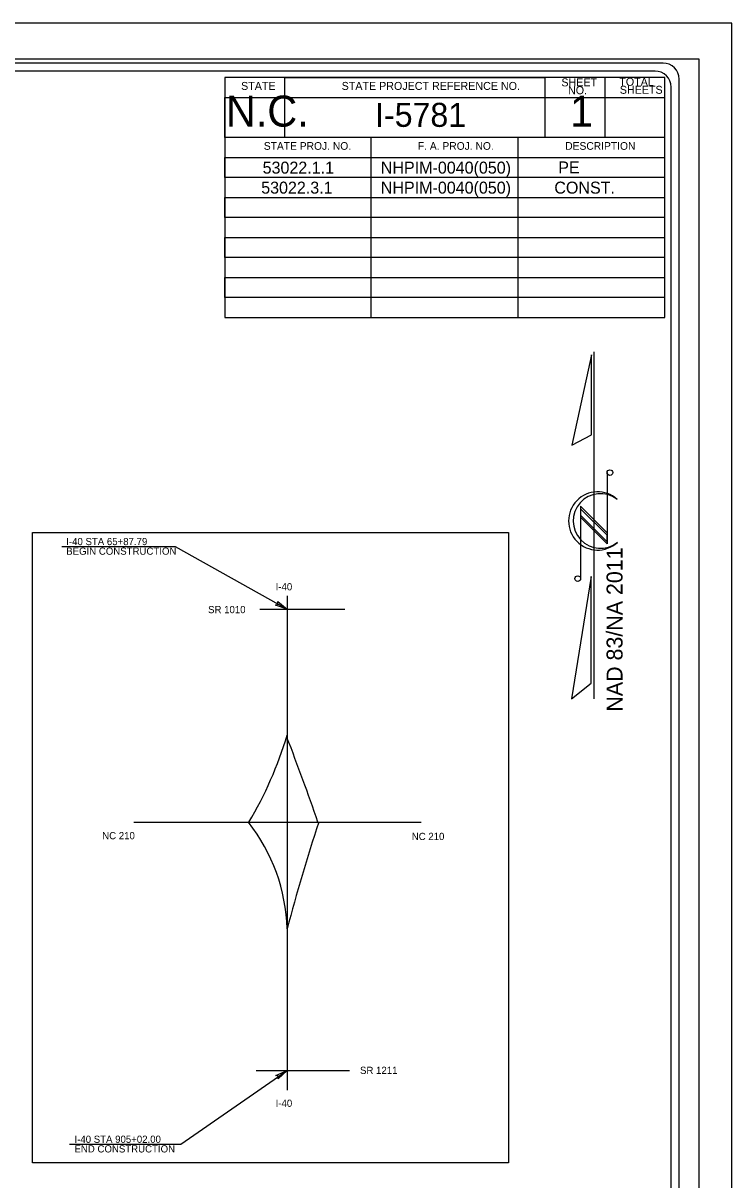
# Model space of a CAD drawing. Extents: x 2128934 to 2134034, y 641595 to 644895.
# Drawn here: x 2132705 to 2134034, y 642727 to 644895 of the extents above; entities that cross this region are included whole.
import ezdxf

# ---------------------------------------------------------------- set-up
doc = ezdxf.new("R2010")
doc.units = 0
for name, color, linetype in [('Prop Dimension Text', 7, 'Continuous'), ('Prop DSN Text', 7, 'Continuous'), ('Prop Horizontal Alignment', 7, 'Continuous'), ('Prop Terminator CELL', 7, 'Continuous'), ('Sheet Data Field CELL', 7, 'Continuous'), ('Sheet North Arrow CELL', 7, 'Continuous'), ('Sheet Plot Border Inside CELL', 7, 'Continuous'), ('Sheet Plot Border Outside CELL', 7, 'Continuous'), ('Sheet Title CELL', 7, 'Continuous')]:
    doc.layers.add(name, color=color, linetype=linetype)

msp = doc.modelspace()

# ---------------------------------------------------------------- linework, layer by layer
at = {"layer": 'Prop Dimension Text'}
for p, q in [((2132777.5, 643914.2), (2132989.6, 643914.2)), ((2132989.6, 643914.2), (2133199.9, 643796.5)), ((2133000.2, 642793.7), (2133199.9, 642931.7)), ((2132791.7, 642793.6), (2133000.2, 642793.7))]:
    msp.add_line(p, q, dxfattribs=at)
at = {"layer": 'Prop DSN Text'}
msp.add_lwpolyline([(2132722.5, 643940.6), (2133614.8, 643940.6), (2133614.8, 642758.6), (2132722.5, 642758.6)], close=True, dxfattribs=at)
at = {"layer": 'Prop Horizontal Alignment'}
for p, q in [((2133199.9, 643821.3), (2133199.9, 642894.9)), ((2133148.4, 643796.5), (2133308.2, 643796.5)), ((2132912.1, 643397.1), (2133451.2, 643397.1)), ((2133141.5, 642931.7), (2133316.5, 642931.7))]:
    msp.add_line(p, q, dxfattribs=at)
for centre, radius, start, end in [((2132503.8, 643770.2), 727.1, 329.1308, 343.2184), ((2128978.9, 641925.5), 4524.7, 18.9803, 21.1256), ((2132859.4, 643187.1), 340.6, 1.7123, 38.08), ((2136013.3, 642470.8), 2905.7, 161.4088, 165.5242)]:
    msp.add_arc(centre, radius, start, end, dxfattribs=at)
at = {"layer": 'Prop Terminator CELL'}
for points in [[(2133182.1, 643810.9), (2133199.9, 643796.5), (2133178.2, 643804.1), (2133182.6, 643806.1)], [(2133178.9, 642922.8), (2133199.9, 642931.7), (2133183, 642916.1), (2133183.3, 642921)]]:
    msp.add_lwpolyline(points, close=True, dxfattribs=at)
at = {"layer": 'Sheet North Arrow CELL'}
for p, q in [((2133775.3, 643628.8), (2133775.3, 644278.8)), ((2133799.8, 644052.6), (2133799.8, 643919.2)), ((2133818.2, 644002.9), (2133818.9, 644002.4)), ((2133799.8, 643940), (2133750.1, 643989.7)), ((2133750.1, 643989.7), (2133750.1, 643854.1)), ((2133799.8, 643935.1), (2133750.1, 643984.8)), ((2133750.1, 643984.8), (2133750.1, 643972.6)), ((2133799.8, 643922.9), (2133750.1, 643972.6)), ((2133750.1, 643972.6), (2133799.8, 643922.9)), ((2133799.8, 643919.2), (2133750.1, 643968.9)), ((2133799.8, 643922.9), (2133799.8, 643935.1))]:
    msp.add_line(p, q, dxfattribs=at)
for points in [[(2133770.8, 644273.1), (2133733.7, 644104.3), (2133770.8, 644123.1)], [(2133770, 643857.8), (2133733.2, 643628.8), (2133770, 643657.8)]]:
    msp.add_lwpolyline(points, close=True, dxfattribs=at)
for centre in [(2133805.1, 644052.5), (2133744.8, 643853.9)]:
    msp.add_circle(centre, 5.3, dxfattribs=at)
for centre, radius, start, end in [((2133782.2, 643962), 54.6, 47.84, 312.3941), ((2133787.5, 643962), 51.2, 53.095, 308.6287)]:
    msp.add_arc(centre, radius, start, end, dxfattribs=at)
at = {"layer": 'Sheet Plot Border Inside CELL'}
msp.add_lwpolyline([(2128972.8, 641662.5), (2133972.3, 641662.5), (2133972.3, 644827.8), (2128972.8, 644827.8)], close=True, dxfattribs=at)
at = {"layer": 'Sheet Plot Border Outside CELL'}
msp.add_lwpolyline([(2128933.8, 641595.1), (2134033.8, 641595.1), (2134033.8, 644895.1), (2128933.8, 644895.1)], close=True, dxfattribs=at)
at = {"layer": 'Sheet Title CELL'}
for points in [[(2133904.8, 644820.1), (2129464.7, 644820.2)], [(2133889.8, 644805.1), (2129629.8, 644805.1)], [(2133082.8, 644343.2), (2133907.8, 644343.2), (2133907.8, 644380.6), (2133082.8, 644380.7), (2133082.8, 644418.1), (2133907.8, 644418.1), (2133907.8, 644455.6), (2133082.8, 644455.6), (2133082.8, 644493.2), (2133907.8, 644493.2), (2133907.8, 644530.7), (2133082.8, 644530.7), (2133082.8, 644568.1), (2133907.8, 644568.2), (2133907.8, 644605.6), (2133082.8, 644605.6), (2133082.8, 644643.1), (2133907.8, 644643.1), (2133907.8, 644680.7), (2133082.8, 644680.7), (2133082.8, 644755.7), (2133907.8, 644755.7), (2133907.8, 644793.2), (2133082.8, 644793.1), (2133082.8, 644343.2), (2133357.7, 644343.1), (2133357.7, 644680.6), (2133195.3, 644680.6), (2133195.3, 644793.2), (2133682.8, 644793.1), (2133682.8, 644680.7), (2133632.7, 644680.7), (2133632.7, 644343.2), (2133907.8, 644343.2), (2133907.8, 644793.2), (2133795.3, 644793.2), (2133795.3, 644680.7)], [(2133919.8, 642270.1), (2133919.8, 644775.2)], [(2133934.8, 641700.2), (2133934.8, 644790.1)]]:
    msp.add_lwpolyline(points, dxfattribs=at)
for centre in [(2133904.8, 644790.3), (2133889.8, 644775.3)]:
    msp.add_arc(centre, 30, 0, 90, dxfattribs=at)

# ---------------------------------------------------------------- texts
at = {"layer": 'Prop Dimension Text'}
for s, p in [('I-40 STA 65+87.79', (2132785.6, 643916.6)), ('BEGIN CONSTRUCTION', (2132785.6, 643898.6)), ('I-40', (2133178.3, 643831.9)), ('SR 1010', (2133051.6, 643789.1)), ('NC 210', (2132853.1, 643365.3)), ('NC 210', (2133433.5, 643363.9)), ('SR 1211', (2133336.5, 642925.4)), ('I-40', (2133178.3, 642863.7)), ('I-40 STA 905+02.00', (2132801.1, 642796.2)), ('END CONSTRUCTION', (2132801.1, 642778.2))]:
    msp.add_text(s, height=13.5, rotation=0.0155, dxfattribs=at).set_placement(p)
at = {"layer": 'Sheet Data Field CELL'}
msp.add_text('I-5781', height=45, rotation=360, dxfattribs=at).set_placement((2133364.8, 644700.7))
for s, p in [('53022.1.1 ', (2133153.9, 644613)), ('NHPIM-0040(050)', (2133375.5, 644613)), ('   PE     ', (2133683.1, 644613.3)), ('NHPIM-0040(050)', (2133375.5, 644575.5)), ('53022.3.1 ', (2133151.2, 644575.5)), (' CONST.   ', (2133692.5, 644575.5))]:
    msp.add_text(s, height=22.5, dxfattribs=at).set_placement(p)
at = {"layer": 'Sheet North Arrow CELL'}
msp.add_text('NAD 83/NA 2011', height=30, rotation=90, dxfattribs=at).set_placement((2133828.8, 643604.6))
at = {"layer": 'Sheet Title CELL'}
for s, height, p in [('STATE', 15, (2133113.5, 644769.9)), ('STATE PROJECT REFERENCE NO.', 14.999, (2133302.1, 644769.9)), ('SHEET', 15, (2133714.1, 644776.6)), ('NO.', 15, (2133726.6, 644761.8)), ('TOTAL', 15, (2133822.7, 644777.7)), ('SHEETS', 15, (2133823.7, 644762.7)), ('N.C.', 58.05, (2133085, 644701.2)), ('1', 58, (2133730.3, 644701.2)), ('STATE PROJ. NO.', 14.4, (2133156.1, 644657.7)), ('F. A. PROJ. NO.', 14.4, (2133445, 644657.7)), ('DESCRIPTION', 14.4, (2133721.3, 644657.7))]:
    msp.add_text(s, height=height, rotation=360, dxfattribs=at).set_placement(p)

doc.saveas('drawing.dxf')
